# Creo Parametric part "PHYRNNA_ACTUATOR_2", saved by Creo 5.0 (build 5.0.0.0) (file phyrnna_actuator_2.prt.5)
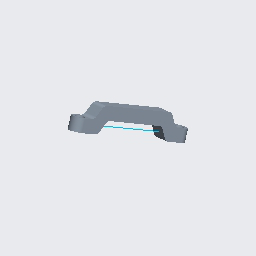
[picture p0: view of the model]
Units: Inch lbm Second (Pro/E Default); INCH, POUND, SECS

Created from: INLBS_PART_SOLID.PRT

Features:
  1. datum plane "RIGHT"
  2. datum plane "TOP"
  3. datum plane "FRONT"
  4. coordinate system
  5. sketch "REFERENCE_2"
  6. datum plane "DTM1", "REFERENCE_2"
  7. sketch "Sketch 2"
  8. protrusion "Swept Blend 1"
  9. round "Round 1"
  10. sketch "Sketch 1"
  11. extrusion "Extrude 1"
  12. sketch "Sketch 2"
  13. extruded cut "Extrude 1"

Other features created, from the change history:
  group "COPIED_GROUP"

Other named items: REFERENCE_1, ACTUATOR_G, ACTUATOR_SW, ACTUATOR_R, ACTUATOR_S, ACTUATOR_E, PEG_HOLE_S, PEG_HOLE_E

Surfaces: 10 plane, 10 cylinder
